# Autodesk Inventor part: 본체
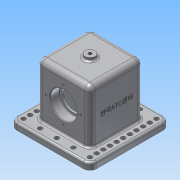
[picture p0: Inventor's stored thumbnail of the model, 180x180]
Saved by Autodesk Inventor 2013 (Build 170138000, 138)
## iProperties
Created: 2018-11
Part Number: 본체
Material: 알루미늄 6061
Document SubType Name: Modeling
Designer: Administrator
Mass: 1020.76 g
Surface Area: 777.082 cm^2
Volume: 376.663 cm^3
Density: 2.71 g/cm^3
Author: Administrator
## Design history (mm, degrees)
sketch "스케치1"
  geometry: L1 (-40, -40)-(40, -40); L2 (40, -40)-(40, 40); L3 (40, 40)-(-40, 40); L4 (-40, 40)-(-40, -40); L5 (-40, -40)-(40, 40); L6 (40, -40)-(-40, 40); 1 further point
  constraints: 12 end point, 2 midpoint, 2 parallel, 1 horizontal, 1 perpendicular
  dimensions: "d0" = 80 distance of L2.end L3.end; "d2" = 80 distance of L1.end L2.end
extrude "돌출1" new body sketch "스케치1" distance "d3" = 90; taper "d4" = 0 deg
sketch "스케치2"
  geometry: L1 (-30, -23)-(30, -23); L2 (30, -23)-(30, 23); L3 (30, 23)-(-30, 23); L4 (-30, 23)-(-30, -23); L5 (-30, -23)-(30, 23); L6 (30, -23)-(-30, 23); 3 further points
  constraints: 12 end point, 3 midpoint, 2 parallel, 1 coincident, 1 horizontal, 1 perpendicular
  dimensions: "d5" = 60 distance of L2.end L3.end; "d7" = 46 distance of L1.end L2.end
extrude "돌출2" cut sketch "스케치2" distance "d8" = 80; taper "d9" = 0 deg
sketch "스케치3"
  geometry: L1 (40, -40)-(-40, -40) reference; L2 (40, 40)-(40, -40) reference; L3 (-40, 40)-(40, 40) reference; L4 (-40, -40)-(-40, 40) reference; L5 (-60, -60)-(60, -60); L6 (60, -60)-(60, 60); L7 (60, 60)-(-60, 60); L8 (-60, 60)-(-60, -60); L9 (-60, -60)-(60, 60); L10 (60, -60)-(-60, 60); 1 further point
  constraints: 12 end point, 2 midpoint, 2 parallel, 1 horizontal, 1 perpendicular
  dimensions: "d10" = 120 distance of L6.end L7.end; "d12" = 120 distance of L5.end L6.end
extrude "돌출3" join sketch "스케치3" distance "d13" = 10; taper "d14" = 0 deg
fillet "모깎기1" dims "d15" = 10
fillet "모깎기2" dims "d16" = 8
fillet "모깎기3" dims "d17" = 8
fillet "모깎기4" dims "d18" = 3
fillet "모깎기5" dims "d19" = 3
sketch "스케치4"
  geometry: L1 (82, -10)-(-18, -10) reference; C1 r 20 at (32, 38); 2 further points
  constraints: 1 centre point, 1 midpoint, 1 vertical alignment
  dimensions: "d20" = 48 distance from line of L1 C1.centre; "d21" = 40 diameter of C1
extrude "돌출4" cut sketch "스케치4" distance "d22" = 14; taper "d23" = 0 deg
sketch "스케치5"
  geometry: C1 r 20 at (0, 0) reference; C2 r 16.5 at (0, 0); 1 further point
  constraints: 1 centre point, 1 coincident
  dimensions: "d24" = 33 diameter of C2
extrude "돌출5" cut sketch "스케치5" distance "d27" = 3; taper "d28" = 0 deg
fillet "모깎기6" dims "d29" = 0.6
chamfer "모따기1" distance "d30" = 1; stored, may be unused: second distance "d31" = 2, angle "d32" = 45 deg
sketch "스케치6" dims "d33" = 52
  geometry: C1 r 21 at (32, 38) reference; 3 further points
  constraints: 2 vertical alignment, 1 coincident, 2 other
hole "구멍1" sketch "스케치6" at (32, 64) diameter "d35" = 3.242; stored, may be unused: countersink angle "d39" = 90 deg, drill point angle "d41" = 118 deg; dims "d36" = 8, "d37" = 4, "d38" = 2, "d40" = 10
fillet "모깎기7" dims "d45" = 3
sketch "스케치7"
  geometry: C1 r 3.3 at (-50, 50); A1 r 10 centre (-50, 50) between (-50, 60) and (-60, 50) reference; 1 further point
  constraints: 1 centre point, 1 coincident
  dimensions: "d46" = 6.6 diameter of C1
extrude "돌출6" cut sketch "스케치7" stored distance "d48" = 3; taper "d49" = 0 deg
sketch "스케치8"
  geometry: L1 (-50, -60)-(50, -60) reference; C1 r 3.3 at (-50, -50) reference; C2 r 3.3 at (-25, -50); 1 further point
  constraints: 1 centre point
  dimensions: "d56" = 6.6 diameter of C2; "d57" = 25 distance of C1.centre C2.centre; "d58" = 10 distance from line of L1 C2.centre
extrude "돌출7" cut sketch "스케치8" stored distance "d59" = 3; taper "d60" = 0 deg
fillet "모깎기8" dims "d67" = 3
sketch "스케치9"
  geometry: C1 r 7.5 at (0, 0); 1 further point
  constraints: 1 centre point, 1 coincident
  dimensions: "d68" = 15 diameter of C1
extrude "돌출8" join sketch "스케치9" distance "d70" = 5; taper "d71" = 0 deg
sketch "스케치10"
  geometry: C1 r 7.5 at (0, 0) reference
hole "구멍2" sketch "스케치10" at (0, 0) diameter "d72" = 4.917; stored, may be unused: countersink angle "d76" = 90 deg, drill point angle "d78" = 118 deg; dims "d73" = 8, "d74" = 4, "d75" = 2, "d77" = 31.75
fillet "모깎기9" dims "d79" = 3
sketch "스케치13"
  geometry: L1 (82, 82)-(82, -18) reference; L2 (0, -8)-(69, -8) reference; 2 further points
  constraints: 1 other
  dimensions: "d80" = 48 distance from line of L1 point (34, 32); "d81" = 40 distance from line of L2 point (34, 32)
extrude "돌출9" join sketch "스케치13" distance "d82" = 0.5; taper "d83" = 0 deg
node "솔리드1"
mirror "대칭1"
pattern_circular "원형 패턴1" dims angle "d43" = 360 deg
mirror "대칭2"
pattern_linear "직사각형 패턴1" dims "d52" = 10
pattern_linear "직사각형 패턴2"
pattern_linear "직사각형 패턴3" dims "d63" = 25
pattern_linear "직사각형 패턴4"
